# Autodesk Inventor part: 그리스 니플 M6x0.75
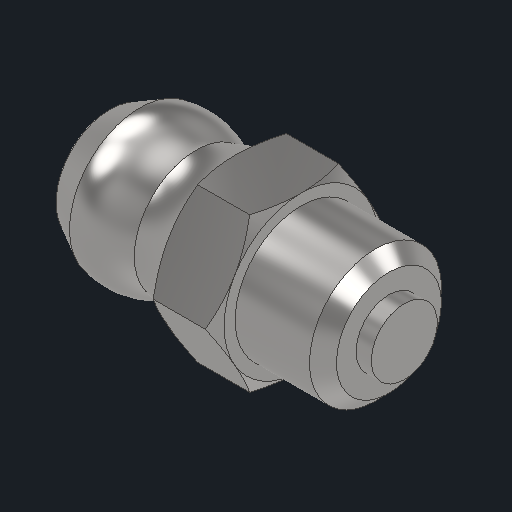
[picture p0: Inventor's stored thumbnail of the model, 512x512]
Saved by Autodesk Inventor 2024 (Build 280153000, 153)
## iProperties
Created: 2025-02
Part Number: 그리스 니플 M6x0.75
Material: 강철, 연강
Description: 윤활 니플, 원추 유형 A
Document SubType Name: Modeling
Designer: kh_501
Density: 7.85 g/cm^3
Appearance: 기본값
Author: jhkim
Sending System: Autodesk Inventor 2025
Preprocessor: ST-DEVELOPER v20
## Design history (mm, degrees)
feature "Solid1"
node "솔리드1"
